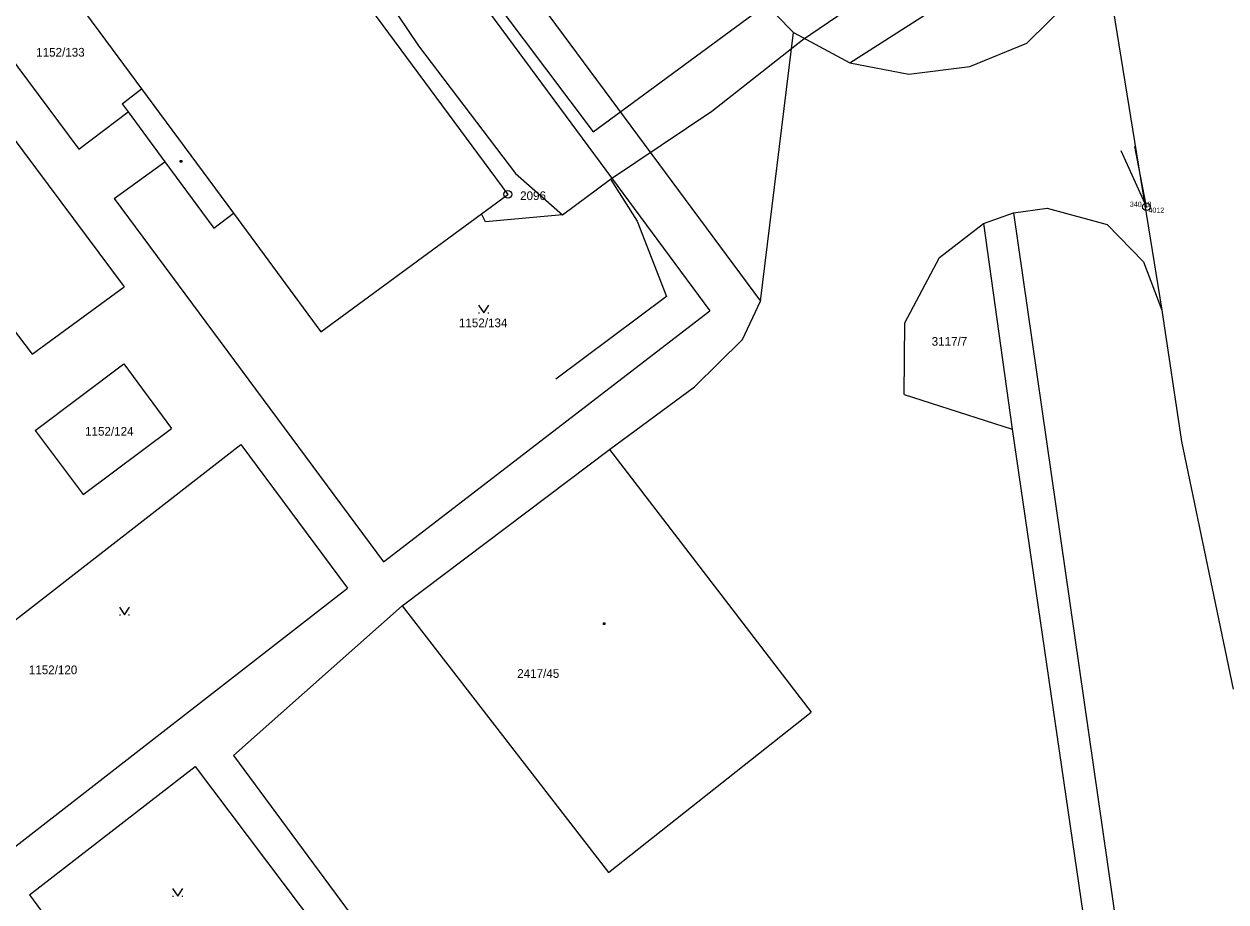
# Model space of a CAD drawing. Extents: x -609709 to -609357, y -1051535 to -1051131.
# Drawn here: x -609542.7 to -609483.9, y -1051431.5 to -1051388.6 of the extents above; entities that cross this region are included whole.
import ezdxf

# ---------------------------------------------------------------- set-up
doc = ezdxf.new("R2010")
doc.units = 0
for name, color, linetype in [('Vrstva 1', 7, 'Continuous'), ('Vrstva 10', 7, 'Continuous'), ('Vrstva 12', 7, 'Continuous'), ('Vrstva 18', 7, 'Continuous'), ('Vrstva 3', 7, 'Continuous')]:
    doc.layers.add(name, color=color, linetype=linetype)

msp = doc.modelspace()

# ---------------------------------------------------------------- linework, layer by layer
at = {"layer": 'Vrstva 1'}
msp.add_line((-609487.79, -1051397.52), (-609487.79, -1051397.52), dxfattribs=at)
at = {"layer": 'Vrstva 10'}
for p, q in [((-609581.79, -1051300.71), (-609506.66, -1051402.14)), ((-609490.24, -1051382.78), (-609487.04, -1051402.58)), ((-609546.85, -1051385.48), (-609539.99, -1051394.71)), ((-609522.05, -1051385.12), (-609509.14, -1051402.6)), ((-609540.97, -1051386.28), (-609538.95, -1051389)), ((-609507.34, -1051386.64), (-609505.05, -1051389)), ((-609548.67, -1051386.83), (-609537.77, -1051401.44)), ((-609502.29, -1051390.48), (-609497.16, -1051387.2)), ((-609525.73, -1051387.84), (-609519.01, -1051396.92)), ((-609493.63, -1051389.53), (-609491.46, -1051387.37)), ((-609538.95, -1051389), (-609536.92, -1051391.76)), ((-609506.66, -1051402.14), (-609505.05, -1051389)), ((-609505.05, -1051389), (-609502.29, -1051390.48)), ((-609496.42, -1051390.67), (-609493.63, -1051389.53)), ((-609502.29, -1051390.48), (-609499.4, -1051391.03)), ((-609499.4, -1051391.03), (-609496.42, -1051390.67)), ((-609537.87, -1051392.49), (-609536.92, -1051391.76)), ((-609536.92, -1051391.76), (-609532.43, -1051397.84)), ((-609537.87, -1051392.49), (-609537.58, -1051392.88)), ((-609539.99, -1051394.71), (-609537.58, -1051392.88)), ((-609537.58, -1051392.88), (-609535.78, -1051395.32)), ((-609538.26, -1051397.11), (-609535.78, -1051395.32)), ((-609535.78, -1051395.32), (-609533.38, -1051398.56)), ((-609535.025, -1051395.265), (-609534.95, -1051395.265)), ((-609535.025, -1051395.34), (-609535.025, -1051395.265)), ((-609534.95, -1051395.34), (-609535.025, -1051395.34)), ((-609534.95, -1051395.265), (-609534.95, -1051395.34)), ((-609538.26, -1051397.11), (-609525.09, -1051414.87)), ((-609528.15, -1051403.63), (-609519.01, -1051396.92)), ((-609495.75, -1051398.34), (-609494.29, -1051397.81)), ((-609494.29, -1051397.81), (-609492.64, -1051397.59)), ((-609494.29, -1051397.81), (-609485.56, -1051458.32)), ((-609492.64, -1051397.59), (-609489.7, -1051398.39)), ((-609533.38, -1051398.56), (-609532.43, -1051397.84)), ((-609532.43, -1051397.84), (-609528.15, -1051403.63)), ((-609497.9, -1051400), (-609495.75, -1051398.34)), ((-609495.75, -1051398.34), (-609494.35, -1051408.39)), ((-609489.7, -1051398.39), (-609487.93, -1051400.22)), ((-609499.6, -1051403.2), (-609497.9, -1051400)), ((-609487.93, -1051400.22), (-609487.04, -1051402.58)), ((-609542.27, -1051404.73), (-609537.77, -1051401.44)), ((-609544.12, -1051402.29), (-609542.27, -1051404.73)), ((-609520.44, -1051402.325), (-609520.19, -1051402.7)), ((-609520.19, -1051402.7), (-609519.94, -1051402.325)), ((-609507.53, -1051404.01), (-609506.66, -1051402.14)), ((-609525.09, -1051414.87), (-609509.14, -1051402.6)), ((-609520.44, -1051402.7), (-609520.39, -1051402.7)), ((-609519.99, -1051402.7), (-609519.94, -1051402.7)), ((-609487.04, -1051402.58), (-609486.07, -1051409)), ((-609499.64, -1051406.7), (-609499.6, -1051403.2)), ((-609509.88, -1051406.33), (-609507.53, -1051404.01)), ((-609542.12, -1051408.46), (-609537.79, -1051405.2)), ((-609537.79, -1051405.2), (-609535.45, -1051408.36)), ((-609514.04, -1051409.38), (-609509.88, -1051406.33)), ((-609499.64, -1051406.7), (-609494.35, -1051408.39)), ((-609539.78, -1051411.59), (-609535.45, -1051408.36)), ((-609494.35, -1051408.39), (-609487.25, -1051457.08)), ((-609542.12, -1051408.46), (-609539.78, -1051411.59)), ((-609548.99, -1051422.29), (-609532.07, -1051409.15)), ((-609532.07, -1051409.15), (-609526.85, -1051416.16)), ((-609524.18, -1051417.03), (-609514.04, -1051409.38)), ((-609514.04, -1051409.38), (-609504.18, -1051422.22)), ((-609486.07, -1051409), (-609483.54, -1051421.1)), ((-609543.79, -1051429.33), (-609526.85, -1051416.16)), ((-609538, -1051417.095), (-609537.75, -1051417.47)), ((-609537.75, -1051417.47), (-609537.5, -1051417.095)), ((-609532.43, -1051424.35), (-609524.18, -1051417.03)), ((-609524.18, -1051417.03), (-609514.09, -1051430.07)), ((-609538, -1051417.47), (-609537.95, -1051417.47)), ((-609537.55, -1051417.47), (-609537.5, -1051417.47)), ((-609514.335, -1051417.865), (-609514.26, -1051417.865)), ((-609514.335, -1051417.94), (-609514.335, -1051417.865)), ((-609514.26, -1051417.94), (-609514.335, -1051417.94)), ((-609514.26, -1051417.865), (-609514.26, -1051417.94)), ((-609514.09, -1051430.07), (-609504.18, -1051422.22)), ((-609532.43, -1051424.35), (-609501.47, -1051466.19)), ((-609542.4, -1051431.15), (-609534.3, -1051424.88)), ((-609534.3, -1051424.88), (-609526.36, -1051435.41)), ((-609542.4, -1051431.15), (-609534.64, -1051441.62)), ((-609535.4, -1051430.855), (-609535.15, -1051431.23)), ((-609535.4, -1051431.23), (-609535.35, -1051431.23)), ((-609535.15, -1051431.23), (-609534.9, -1051430.855)), ((-609534.95, -1051431.23), (-609534.9, -1051431.23))]:
    msp.add_line(p, q, dxfattribs=at)
for radius in [0.188, 0.0025]:
    msp.add_circle((-609519.01, -1051396.91), radius, dxfattribs=at)
at = {"layer": 'Vrstva 12'}
for points in [[(-609615.546, -1051325.052), (-609614.108, -1051326.974), (-609589.099, -1051308.266), (-609582.815, -1051303.565), (-609514.844, -1051393.856), (-609499.807, -1051382.785), (-609467.693, -1051377.467)], [(-609513.99, -1051396.17), (-609509.03, -1051392.84), (-609504.6, -1051389.36), (-609497.48, -1051384.5), (-609490.61, -1051381.13), (-609487.01, -1051379.99), (-609478.64, -1051378.48), (-609473.03, -1051377.23), (-609472.37, -1051375.01), (-609472.654, -1051372.8)], [(-609524.39, -1051388.15), (-609523.38, -1051389.65), (-609518.63, -1051395.89), (-609516.34, -1051397.91), (-609520.11, -1051398.25), (-609520.283, -1051397.9)], [(-609516.34, -1051397.91), (-609513.99, -1051396.17), (-609512.68, -1051398.22)], [(-609512.68, -1051398.22), (-609511.25, -1051401.9), (-609516.67, -1051405.94)]]:
    msp.add_lwpolyline(points, dxfattribs=at)
at = {"layer": 'Vrstva 18'}
for points in [[(-609487.79, -1051397.52), (-609489.022, -1051394.785)], [(-609487.79, -1051397.52), (-609488.358, -1051394.574)]]:
    msp.add_lwpolyline(points, dxfattribs=at)
for radius in [0.188, 0.025]:
    msp.add_circle((-609487.79, -1051397.52), radius, dxfattribs=at)

# ---------------------------------------------------------------- texts
at = {"layer": 'Vrstva 10'}
for s, p in [('1152/133', (-609542.07, -1051390.18)), ('2096', (-609518.41, -1051397.192)), ('1152/134', (-609521.402, -1051403.408)), ('3117/7', (-609498.288, -1051404.314)), ('1152/124', (-609539.68, -1051408.71)), ('1152/120', (-609542.43, -1051420.37)), ('2417/45', (-609518.55, -1051420.55))]:
    msp.add_text(s, height=0.425, dxfattribs=at).set_placement(p)
at = {"layer": 'Vrstva 18'}
msp.add_text(' 4012', height=0.25, dxfattribs=at).set_placement((-609487.78, -1051397.81))
at = {"layer": 'Vrstva 3'}
msp.add_text('340.13', height=0.25, dxfattribs=at).set_placement((-609488.598, -1051397.52))

doc.saveas('drawing.dxf')
